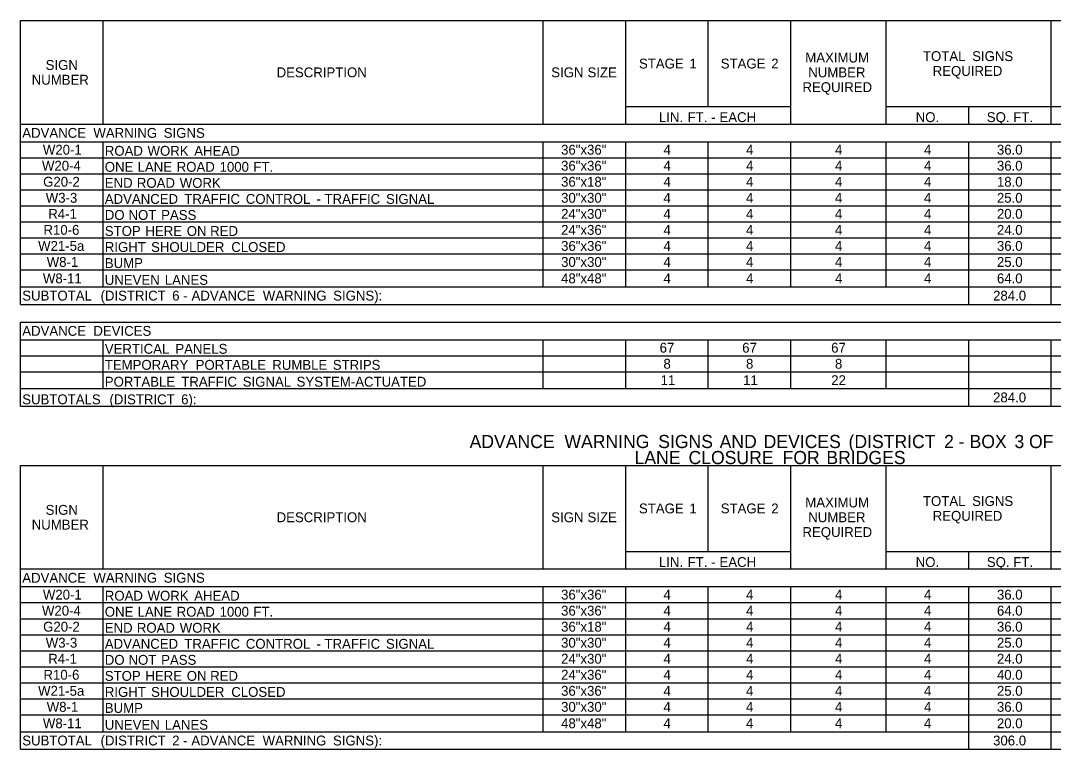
# Model space of a CAD drawing. Extents: x 542596 to 1930787, y -1948294 to 596640.
# Drawn here: x 544436 to 545065, y -1946796 to -1946353 of the extents above; entities that cross this region are included whole.
import ezdxf

# ---------------------------------------------------------------- set-up
doc = ezdxf.new("R2010")
doc.units = 0
doc.layers.add('Default', color=7, linetype='Continuous')

msp = doc.modelspace()

# ---------------------------------------------------------------- linework, layer by layer
at = {"layer": 'Default'}
for p, q in [((544436.43, -1946352.99), (545325.15, -1946352.99)), ((544436.43, -1946525.56), (544436.43, -1946352.99)), ((544436.43, -1946525.56), (544436.43, -1946352.99)), ((544486.65, -1946415.87), (544486.65, -1946352.99)), ((544754.28, -1946415.87), (544754.28, -1946352.99)), ((544804.5, -1946415.87), (544804.5, -1946352.99)), ((544854.71, -1946405.15), (544854.71, -1946352.99)), ((544904.92, -1946415.87), (544904.92, -1946352.99)), ((544962.93, -1946415.87), (544962.93, -1946352.99)), ((545063.36, -1946415.87), (545063.36, -1946352.99)), ((544804.5, -1946405.15), (544904.92, -1946405.15)), ((544904.92, -1946415.87), (544904.92, -1946405.15)), ((544962.93, -1946405.15), (545325.15, -1946405.15)), ((545013.15, -1946415.87), (545013.15, -1946405.15)), ((545063.36, -1946415.87), (545063.36, -1946405.15)), ((544436.43, -1946415.87), (545325.15, -1946415.87)), ((544904.92, -1946415.87), (545063.36, -1946415.87)), ((545063.36, -1946415.87), (545115.52, -1946415.87)), ((544436.43, -1946426.6), (545325.15, -1946426.6)), ((544486.65, -1946514.84), (544486.65, -1946426.6)), ((544486.65, -1946514.84), (544486.65, -1946426.6)), ((544754.28, -1946514.84), (544754.28, -1946426.6)), ((544754.28, -1946514.84), (544754.28, -1946426.6)), ((544804.5, -1946514.84), (544804.5, -1946426.6)), ((544804.5, -1946514.84), (544804.5, -1946426.6)), ((544854.71, -1946504.6), (544854.71, -1946426.6)), ((544854.71, -1946514.84), (544854.71, -1946426.6)), ((544904.92, -1946514.84), (544904.92, -1946426.6)), ((544904.92, -1946514.84), (544904.92, -1946426.6)), ((544962.93, -1946514.84), (544962.93, -1946426.6)), ((545013.15, -1946514.84), (545013.15, -1946426.6)), ((545013.15, -1946525.56), (545013.15, -1946426.6)), ((545063.36, -1946504.6), (545063.36, -1946426.6)), ((545063.36, -1946525.56), (545063.36, -1946426.6)), ((544436.43, -1946436.35), (545325.15, -1946436.35)), ((544436.43, -1946446.1), (545325.15, -1946446.1)), ((544436.43, -1946455.85), (545325.15, -1946455.85)), ((544436.43, -1946465.6), (545325.15, -1946465.6)), ((544436.43, -1946475.35), (545325.15, -1946475.35)), ((544436.43, -1946485.1), (545325.15, -1946485.1)), ((544436.43, -1946494.85), (545325.15, -1946494.85)), ((544436.43, -1946504.6), (545325.15, -1946504.6)), ((544436.43, -1946514.84), (545325.15, -1946514.84)), ((544436.43, -1946514.84), (545325.15, -1946514.84)), ((544436.43, -1946525.56), (545325.15, -1946525.56)), ((544436.43, -1946536.29), (545325.15, -1946536.29)), ((544436.43, -1946587.47), (544436.43, -1946536.29)), ((544436.43, -1946587.47), (544436.43, -1946536.29)), ((544486.65, -1946536.29), (545237.4, -1946536.29)), ((544436.43, -1946547.01), (545325.15, -1946547.01)), ((544486.65, -1946576.75), (544486.65, -1946547.01)), ((544486.65, -1946576.75), (544486.65, -1946547.01)), ((544754.28, -1946576.75), (544754.28, -1946547.01)), ((544754.28, -1946576.75), (544754.28, -1946547.01)), ((544804.5, -1946576.75), (544804.5, -1946547.01)), ((544804.5, -1946576.75), (544804.5, -1946547.01)), ((544854.71, -1946576.75), (544854.71, -1946547.01)), ((544854.71, -1946576.75), (544854.71, -1946547.01)), ((544904.92, -1946576.75), (544904.92, -1946547.01)), ((544904.92, -1946576.75), (544904.92, -1946547.01)), ((544962.93, -1946576.75), (544962.93, -1946547.01)), ((545013.15, -1946576.75), (545013.15, -1946547.01)), ((545013.15, -1946587.47), (545013.15, -1946547.01)), ((545063.36, -1946587.47), (545063.36, -1946547.01)), ((545063.36, -1946587.47), (545063.36, -1946547.01)), ((544436.43, -1946556.76), (545325.15, -1946556.76)), ((544436.43, -1946566.51), (545325.15, -1946566.51)), ((544436.43, -1946576.75), (545325.15, -1946576.75)), ((544436.43, -1946576.75), (545325.15, -1946576.75)), ((544436.43, -1946587.47), (545325.15, -1946587.47)), ((544436.43, -1946623.55), (545325.15, -1946623.55)), ((544436.43, -1946796.12), (544436.43, -1946623.55)), ((544436.43, -1946796.12), (544436.43, -1946623.55)), ((544486.65, -1946686.44), (544486.65, -1946623.55)), ((544754.28, -1946686.44), (544754.28, -1946623.55)), ((544804.5, -1946686.44), (544804.5, -1946623.55)), ((544854.71, -1946675.71), (544854.71, -1946623.55)), ((544904.92, -1946686.44), (544904.92, -1946623.55)), ((544962.93, -1946686.44), (544962.93, -1946623.55)), ((545063.36, -1946686.44), (545063.36, -1946623.55)), ((544804.5, -1946675.71), (544904.92, -1946675.71)), ((544904.92, -1946686.44), (544904.92, -1946675.71)), ((544962.93, -1946675.71), (545325.15, -1946675.71)), ((545013.15, -1946686.44), (545013.15, -1946675.71)), ((544436.43, -1946686.44), (545325.15, -1946686.44)), ((544904.92, -1946686.44), (545325.15, -1946686.44)), ((544436.43, -1946697.16), (545325.15, -1946697.16)), ((544486.65, -1946785.4), (544486.65, -1946697.16)), ((544486.65, -1946785.4), (544486.65, -1946697.16)), ((544754.28, -1946785.4), (544754.28, -1946697.16)), ((544754.28, -1946785.4), (544754.28, -1946697.16)), ((544804.5, -1946785.4), (544804.5, -1946697.16)), ((544804.5, -1946785.4), (544804.5, -1946697.16)), ((544854.71, -1946775.16), (544854.71, -1946697.16)), ((544854.71, -1946785.4), (544854.71, -1946697.16)), ((544904.92, -1946785.4), (544904.92, -1946697.16)), ((544904.92, -1946785.4), (544904.92, -1946697.16)), ((544962.93, -1946785.4), (544962.93, -1946697.16)), ((545013.15, -1946785.4), (545013.15, -1946697.16)), ((545013.15, -1946796.12), (545013.15, -1946697.16)), ((545063.36, -1946796.12), (545063.36, -1946697.16)), ((545063.36, -1946796.12), (545063.36, -1946697.16)), ((544436.43, -1946706.91), (545325.15, -1946706.91)), ((544436.43, -1946716.66), (545325.15, -1946716.66)), ((544436.43, -1946726.41), (545325.15, -1946726.41)), ((544436.43, -1946736.16), (545325.15, -1946736.16)), ((544436.43, -1946745.91), (545325.15, -1946745.91)), ((544436.43, -1946755.66), (545325.15, -1946755.66)), ((544436.43, -1946765.41), (545325.15, -1946765.41)), ((544436.43, -1946775.16), (545325.15, -1946775.16)), ((544436.43, -1946785.4), (545013.15, -1946785.4)), ((544436.43, -1946785.4), (545325.15, -1946785.4)), ((544436.43, -1946796.12), (545325.15, -1946796.12))]:
    msp.add_line(p, q, dxfattribs=at)

# ---------------------------------------------------------------- texts
for s, height, p in [('STAGE', 6, (544812.55, -1946382.07)), (' 1', 6, (544841.02, -1946382.07)), ('STAGE', 6, (544862.3, -1946382.07)), (' 2', 6, (544890.77, -1946382.07)), ('MAXIMUM', 6, (544913.74, -1946378.43)), ('TOTAL', 6, (544985.3, -1946377.57)), (' SIGNS', 6, (545012.99, -1946377.57)), ('SIGN', 6, (544451.63, -1946382.93)), ('DESCRIPTION', 6, (544592.15, -1946387.43)), ('SIGN', 6, (544759.2, -1946387.43)), (' SIZE', 6, (544779.03, -1946387.43)), ('NUMBER', 6, (544915.55, -1946387.43)), ('REQUIRED', 6, (544991.23, -1946386.57)), ('NUMBER', 6, (544443.16, -1946391.93)), ('REQUIRED', 6, (544912.01, -1946396.43)), ('LIN.', 6, (544824.67, -1946414.67)), (' FT.', 6, (544839.93, -1946414.67)), (' -', 6, (544854.25, -1946414.67)), (' EACH', 6, (544859.31, -1946414.67)), ('NO.', 6, (544980.88, -1946414.67)), ('SQ.', 6, (545024.16, -1946414.67)), (' FT.', 6, (545038.02, -1946414.67)), ('ADVANCE', 6, (544437.41, -1946424.24)), (' WARNING', 6, (544478.45, -1946424.24)), (' SIGNS', 6, (544521.25, -1946424.24)), ('W20-1', 6, (544449.97, -1946434.47)), ('ROAD', 6, (544487.62, -1946435.15)), (' WORK', 6, (544511.4, -1946435.15)), (' AHEAD', 6, (544539.79, -1946435.15)), ('36"x36"', 6, (544765.19, -1946434.47)), ('4', 6, (544827.48, -1946434.47)), ('4', 6, (544877.69, -1946434.47)), ('4', 6, (544931.8, -1946434.47)), ('4', 6, (544985.91, -1946434.47)), ('36.0', 6, (545030.3, -1946434.47)), ('W20-4', 6, (544449.4, -1946444.22)), ('ONE', 6, (544487.62, -1946444.9)), (' LANE', 6, (544505.34, -1946444.9)), (' ROAD', 6, (544529.12, -1946444.9)), (' 1000', 6, (544555.23, -1946444.9)), (' FT.', 6, (544575.79, -1946444.9)), ('36"x36"', 6, (544765.19, -1946444.22)), ('4', 6, (544827.48, -1946444.22)), ('4', 6, (544877.69, -1946444.22)), ('4', 6, (544931.8, -1946444.22)), ('4', 6, (544985.91, -1946444.22)), ('36.0', 6, (545030.3, -1946444.22)), ('G20-2', 6, (544450.12, -1946453.97)), ('END', 6, (544487.62, -1946454.65)), (' ROAD', 6, (544504.88, -1946454.65)), (' WORK', 6, (544530.98, -1946454.65)), ('36"x18"', 6, (544765.19, -1946453.97)), ('4', 6, (544827.48, -1946453.97)), ('4', 6, (544877.69, -1946453.97)), ('4', 6, (544931.8, -1946453.97)), ('4', 6, (544985.91, -1946453.97)), ('18.0', 6, (545030.3, -1946453.97)), ('W3-3', 6, (544451.72, -1946463.72)), ('30"x30"', 6, (544765.19, -1946463.72)), ('4', 6, (544827.48, -1946463.72)), ('4', 6, (544877.69, -1946463.72)), ('4', 6, (544931.8, -1946463.72)), ('4', 6, (544985.91, -1946463.72)), ('25.0', 6, (545030.3, -1946463.72)), ('ADVANCED', 6, (544487.62, -1946464.4)), (' TRAFFIC', 6, (544533.77, -1946464.4)), (' CONTROL', 6, (544571.16, -1946464.4)), (' -', 6, (544614.18, -1946464.4)), (' TRAFFIC', 6, (544619.03, -1946464.4)), (' SIGNAL', 6, (544656.42, -1946464.4)), ('R4-1', 6, (544453.23, -1946473.47)), ('DO', 6, (544487.62, -1946474.15)), (' NOT', 6, (544499.82, -1946474.15)), (' PASS', 6, (544519.68, -1946474.15)), ('24"x30"', 6, (544765.19, -1946473.47)), ('4', 6, (544827.48, -1946473.47)), ('4', 6, (544877.69, -1946473.47)), ('4', 6, (544931.8, -1946473.47)), ('4', 6, (544985.91, -1946473.47)), ('20.0', 6, (545030.3, -1946473.47)), ('R10-6', 6, (544450.32, -1946483.22)), ('STOP', 6, (544487.62, -1946483.9)), (' HERE', 6, (544510.09, -1946483.9)), (' ON', 6, (544535.26, -1946483.9)), (' RED', 6, (544549.48, -1946483.9)), ('24"x36"', 6, (544765.19, -1946483.22)), ('4', 6, (544827.48, -1946483.22)), ('4', 6, (544877.69, -1946483.22)), ('4', 6, (544931.8, -1946483.22)), ('4', 6, (544985.91, -1946483.22)), ('24.0', 6, (545030.3, -1946483.22)), ('W21-5a', 6, (544447.05, -1946492.97)), ('RIGHT', 6, (544487.62, -1946493.65)), (' SHOULDER', 6, (544513.53, -1946493.65)), (' CLOSED', 6, (544562.33, -1946493.65)), ('36"x36"', 6, (544765.19, -1946492.97)), ('4', 6, (544827.48, -1946492.97)), ('4', 6, (544877.69, -1946492.97)), ('4', 6, (544931.8, -1946492.97)), ('4', 6, (544985.91, -1946492.97)), ('36.0', 6, (545030.3, -1946492.97)), ('W8-1', 6, (544452.3, -1946502.72)), ('BUMP', 6, (544487.62, -1946503.4)), ('30"x30"', 6, (544765.19, -1946502.72)), ('4', 6, (544827.48, -1946502.72)), ('4', 6, (544877.69, -1946502.72)), ('4', 6, (544931.8, -1946502.72)), ('4', 6, (544985.91, -1946502.72)), ('25.0', 6, (545030.3, -1946502.72)), ('W8-11', 6, (544449.97, -1946512.72)), ('UNEVEN', 6, (544487.62, -1946513.64)), (' LANES', 6, (544521.88, -1946513.64)), ('48"x48"', 6, (544765.19, -1946512.72)), ('4', 6, (544827.48, -1946512.72)), ('4', 6, (544877.69, -1946512.72)), ('4', 6, (544931.8, -1946512.72)), ('4', 6, (544985.91, -1946512.72)), ('64.0', 6, (545030.3, -1946512.72)), ('SUBTOTAL', 6, (544437.41, -1946523.2)), (' (DISTRICT', 6, (544482.8, -1946523.2)), (' 6', 6, (544526.4, -1946523.2)), (' -', 6, (544533.09, -1946523.2)), (' ADVANCE', 6, (544538.15, -1946523.2)), (' WARNING', 6, (544581.52, -1946523.2)), (' SIGNS):', 6, (544624.32, -1946523.2)), ('284.0', 6, (545027.97, -1946523.2)), ('ADVANCE', 6, (544437.41, -1946544.65)), (' DEVICES', 6, (544478.45, -1946544.65)), ('VERTICAL', 6, (544487.62, -1946555.56)), (' PANELS', 6, (544528.32, -1946555.56)), ('67', 6, (544825.13, -1946554.89)), ('67', 6, (544875.35, -1946554.89)), ('67', 6, (544929.46, -1946554.89)), ('8', 6, (544827.46, -1946564.64)), ('8', 6, (544877.67, -1946564.64)), ('8', 6, (544931.78, -1946564.64)), ('TEMPORARY', 6, (544487.62, -1946565.31)), (' PORTABLE', 6, (544540.67, -1946565.31)), (' RUMBLE', 6, (544587.28, -1946565.31)), (' STRIPS', 6, (544624.09, -1946565.31)), ('PORTABLE', 6, (544487.62, -1946575.55)), (' TRAFFIC', 6, (544531.9, -1946575.55)), (' SIGNAL', 6, (544569.29, -1946575.55)), (' SYSTEM-ACTUATED', 6, (544602.07, -1946575.55)), ('11', 6, (544825.71, -1946574.63)), ('11', 6, (544875.93, -1946574.63)), ('22', 6, (544929.49, -1946574.63)), ('SUBTOTALS', 6, (544437.41, -1946586.27)), (' (DISTRICT', 6, (544488.24, -1946586.27)), (' 6):', 6, (544531.84, -1946586.27)), ('284.0', 6, (545027.97, -1946585.11)), ('ADVANCE', 8, (544709.52, -1946612.92)), (' WARNING', 8, (544764.25, -1946612.92)), (' SIGNS', 8, (544821.31, -1946612.92)), (' AND', 8, (544858.65, -1946612.92)), (' DEVICES', 8, (544885.42, -1946612.92)), (' (DISTRICT', 8, (544937.06, -1946612.92)), (' 2', 8, (544995.19, -1946612.92)), (' BOX', 8, (545010.69, -1946612.92)), (' 3', 8, (545038.01, -1946612.92)), (' OF', 8, (545046.84, -1946612.92)), ('LANE', 8, (544809.86, -1946622.67)), (' CLOSURE', 8, (544839.73, -1946622.67)), (' FOR', 8, (544896.94, -1946622.67)), (' BRIDGES', 8, (544923.59, -1946622.67)), (' -', 8, (545003.95, -1946612.92)), ('STAGE', 6, (544812.55, -1946652.63)), (' 1', 6, (544841.02, -1946652.63)), ('STAGE', 6, (544862.3, -1946652.63)), (' 2', 6, (544890.77, -1946652.63)), ('MAXIMUM', 6, (544913.74, -1946648.99)), ('TOTAL', 6, (544985.3, -1946648.13)), (' SIGNS', 6, (545012.99, -1946648.13)), ('SIGN', 6, (544451.63, -1946653.49)), ('DESCRIPTION', 6, (544592.15, -1946657.99)), ('SIGN', 6, (544759.2, -1946657.99)), (' SIZE', 6, (544779.03, -1946657.99)), ('NUMBER', 6, (544915.55, -1946657.99)), ('REQUIRED', 6, (544991.23, -1946657.13)), ('NUMBER', 6, (544443.16, -1946662.49)), ('REQUIRED', 6, (544912.01, -1946666.99)), ('LIN.', 6, (544824.67, -1946685.24)), (' FT.', 6, (544839.93, -1946685.24)), (' -', 6, (544854.25, -1946685.24)), (' EACH', 6, (544859.31, -1946685.24)), ('NO.', 6, (544980.88, -1946685.24)), ('SQ.', 6, (545024.16, -1946685.24)), (' FT.', 6, (545038.02, -1946685.24)), ('ADVANCE', 6, (544437.41, -1946694.8)), (' WARNING', 6, (544478.45, -1946694.8)), (' SIGNS', 6, (544521.25, -1946694.8)), ('W20-1', 6, (544449.97, -1946705.04)), ('ROAD', 6, (544487.62, -1946705.71)), (' WORK', 6, (544511.4, -1946705.71)), (' AHEAD', 6, (544539.79, -1946705.71)), ('36"x36"', 6, (544765.19, -1946705.04)), ('4', 6, (544827.48, -1946705.04)), ('4', 6, (544877.69, -1946705.04)), ('4', 6, (544931.8, -1946705.04)), ('4', 6, (544985.91, -1946705.04)), ('36.0', 6, (545030.3, -1946705.04)), ('W20-4', 6, (544449.4, -1946714.79)), ('ONE', 6, (544487.62, -1946715.46)), (' LANE', 6, (544505.34, -1946715.46)), (' ROAD', 6, (544529.12, -1946715.46)), (' 1000', 6, (544555.23, -1946715.46)), (' FT.', 6, (544575.79, -1946715.46)), ('36"x36"', 6, (544765.19, -1946714.79)), ('4', 6, (544827.48, -1946714.79)), ('4', 6, (544877.69, -1946714.79)), ('4', 6, (544931.8, -1946714.79)), ('4', 6, (544985.91, -1946714.79)), ('64.0', 6, (545030.3, -1946714.79)), ('G20-2', 6, (544450.12, -1946724.54)), ('END', 6, (544487.62, -1946725.21)), (' ROAD', 6, (544504.88, -1946725.21)), (' WORK', 6, (544530.98, -1946725.21)), ('36"x18"', 6, (544765.19, -1946724.54)), ('4', 6, (544827.48, -1946724.54)), ('4', 6, (544877.69, -1946724.54)), ('4', 6, (544931.8, -1946724.54)), ('4', 6, (544985.91, -1946724.54)), ('36.0', 6, (545030.3, -1946724.54)), ('W3-3', 6, (544451.72, -1946734.29)), ('30"x30"', 6, (544765.19, -1946734.29)), ('4', 6, (544827.48, -1946734.29)), ('4', 6, (544877.69, -1946734.29)), ('4', 6, (544931.8, -1946734.29)), ('4', 6, (544985.91, -1946734.29)), ('25.0', 6, (545030.3, -1946734.29)), ('ADVANCED', 6, (544487.62, -1946734.96)), (' TRAFFIC', 6, (544533.77, -1946734.96)), (' CONTROL', 6, (544571.16, -1946734.96)), (' -', 6, (544614.18, -1946734.96)), (' TRAFFIC', 6, (544619.03, -1946734.96)), (' SIGNAL', 6, (544656.42, -1946734.96)), ('R4-1', 6, (544453.23, -1946744.04)), ('DO', 6, (544487.62, -1946744.71)), (' NOT', 6, (544499.82, -1946744.71)), (' PASS', 6, (544519.68, -1946744.71)), ('24"x30"', 6, (544765.19, -1946744.04)), ('4', 6, (544827.48, -1946744.04)), ('4', 6, (544877.69, -1946744.04)), ('4', 6, (544931.8, -1946744.04)), ('4', 6, (544985.91, -1946744.04)), ('24.0', 6, (545030.3, -1946744.04)), ('R10-6', 6, (544450.32, -1946753.79)), ('STOP', 6, (544487.62, -1946754.46)), (' HERE', 6, (544510.09, -1946754.46)), (' ON', 6, (544535.26, -1946754.46)), (' RED', 6, (544549.48, -1946754.46)), ('24"x36"', 6, (544765.19, -1946753.79)), ('4', 6, (544827.48, -1946753.79)), ('4', 6, (544877.69, -1946753.79)), ('4', 6, (544931.8, -1946753.79)), ('4', 6, (544985.91, -1946753.79)), ('40.0', 6, (545030.3, -1946753.79)), ('W21-5a', 6, (544447.05, -1946763.54)), ('RIGHT', 6, (544487.62, -1946764.21)), (' SHOULDER', 6, (544513.53, -1946764.21)), (' CLOSED', 6, (544562.33, -1946764.21)), ('36"x36"', 6, (544765.19, -1946763.54)), ('4', 6, (544827.48, -1946763.54)), ('4', 6, (544877.69, -1946763.54)), ('4', 6, (544931.8, -1946763.54)), ('4', 6, (544985.91, -1946763.54)), ('25.0', 6, (545030.3, -1946763.54)), ('W8-1', 6, (544452.3, -1946773.29)), ('BUMP', 6, (544487.62, -1946773.96)), ('30"x30"', 6, (544765.19, -1946773.29)), ('4', 6, (544827.48, -1946773.29)), ('4', 6, (544877.69, -1946773.29)), ('4', 6, (544931.8, -1946773.29)), ('4', 6, (544985.91, -1946773.29)), ('36.0', 6, (545030.3, -1946773.29)), ('W8-11', 6, (544449.97, -1946783.28)), ('UNEVEN', 6, (544487.62, -1946784.2)), (' LANES', 6, (544521.88, -1946784.2)), ('48"x48"', 6, (544765.19, -1946783.28)), ('4', 6, (544827.48, -1946783.28)), ('4', 6, (544877.69, -1946783.28)), ('4', 6, (544931.8, -1946783.28)), ('4', 6, (544985.91, -1946783.28)), ('20.0', 6, (545030.3, -1946783.28)), ('SUBTOTAL', 6, (544437.41, -1946793.76)), (' (DISTRICT', 6, (544482.8, -1946793.76)), (' 2', 6, (544526.4, -1946793.76)), (' -', 6, (544532.97, -1946793.76)), (' ADVANCE', 6, (544538.03, -1946793.76)), (' WARNING', 6, (544581.4, -1946793.76)), (' SIGNS):', 6, (544624.2, -1946793.76)), ('306.0', 6, (545027.97, -1946793.76))]:
    msp.add_text(s, height=height, dxfattribs=at).set_placement(p)

doc.saveas('drawing.dxf')
